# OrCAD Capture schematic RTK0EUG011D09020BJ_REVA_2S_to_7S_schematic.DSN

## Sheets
1 3_BiasSupplies: size C; title: Type-C PD Battery Charger (PB3 Shrink): Bias Supplies; rev: A; note: RTK0EUG011D09020BJ (2S to 7S)
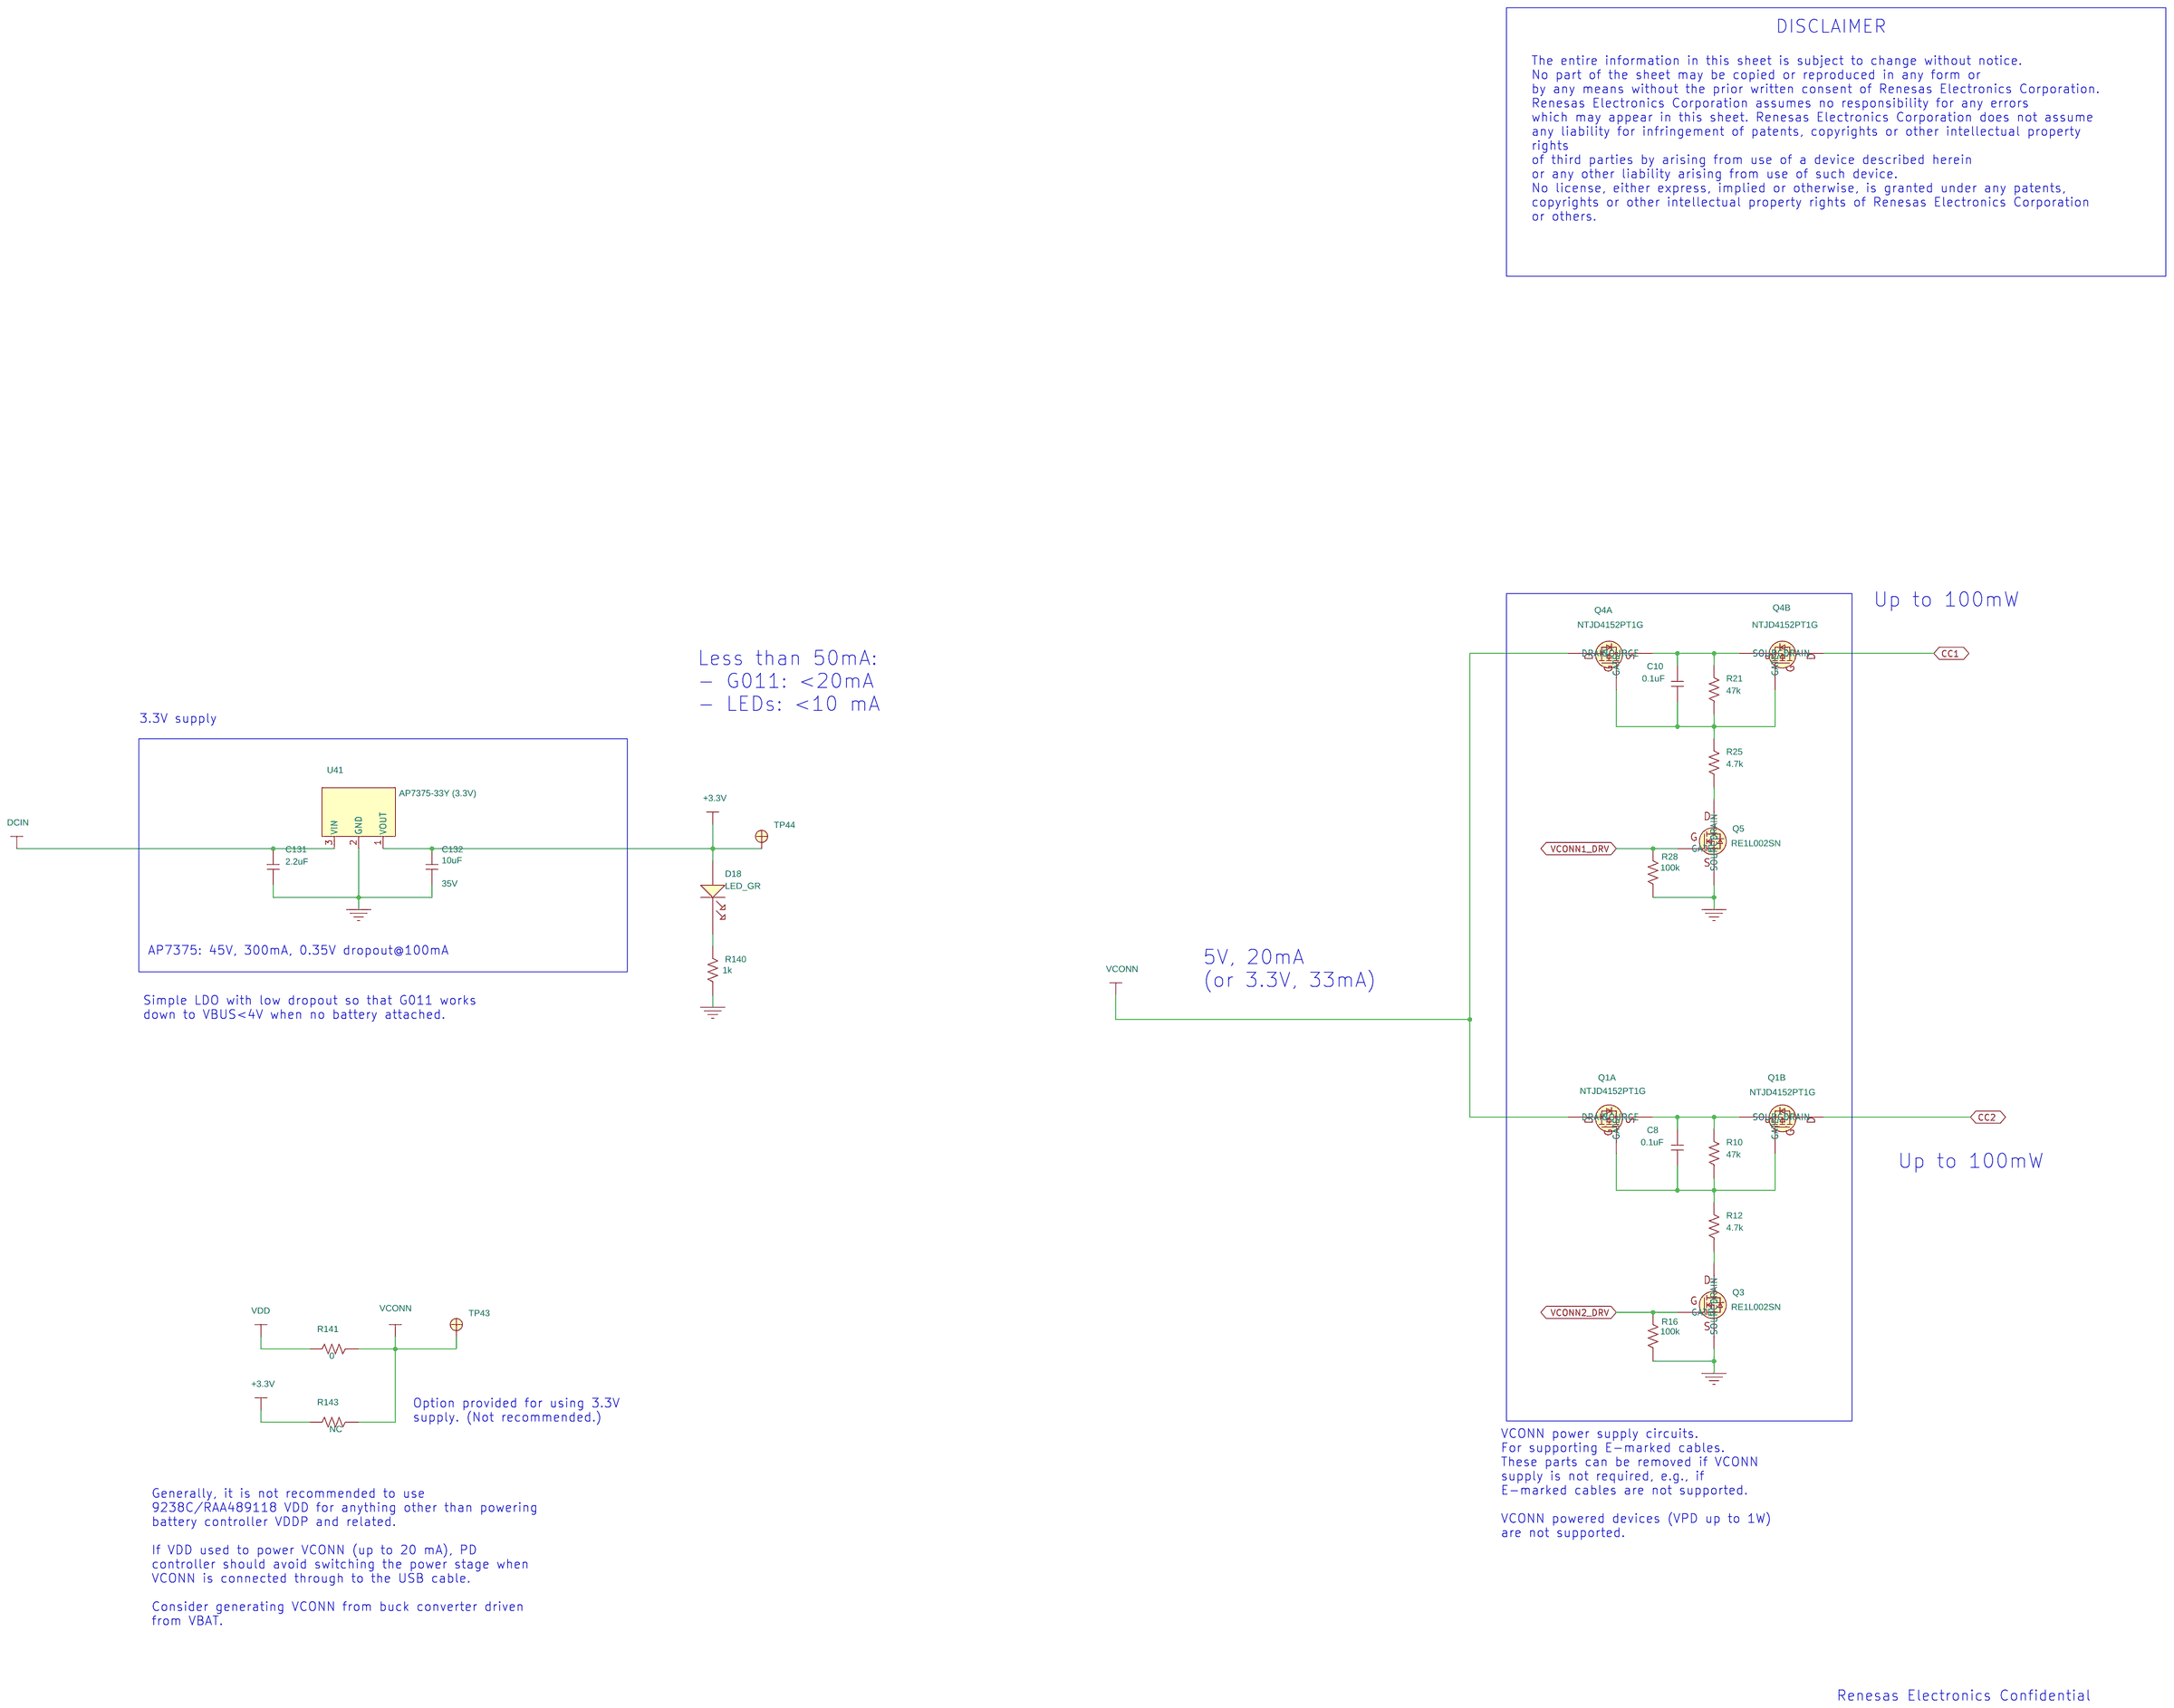
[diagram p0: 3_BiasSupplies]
2 1_Type-C R9A02G011: size C; title: Type-C PD Battery Charger: R9A02G011; note: Draft: RTK0EUG011D09020BJ
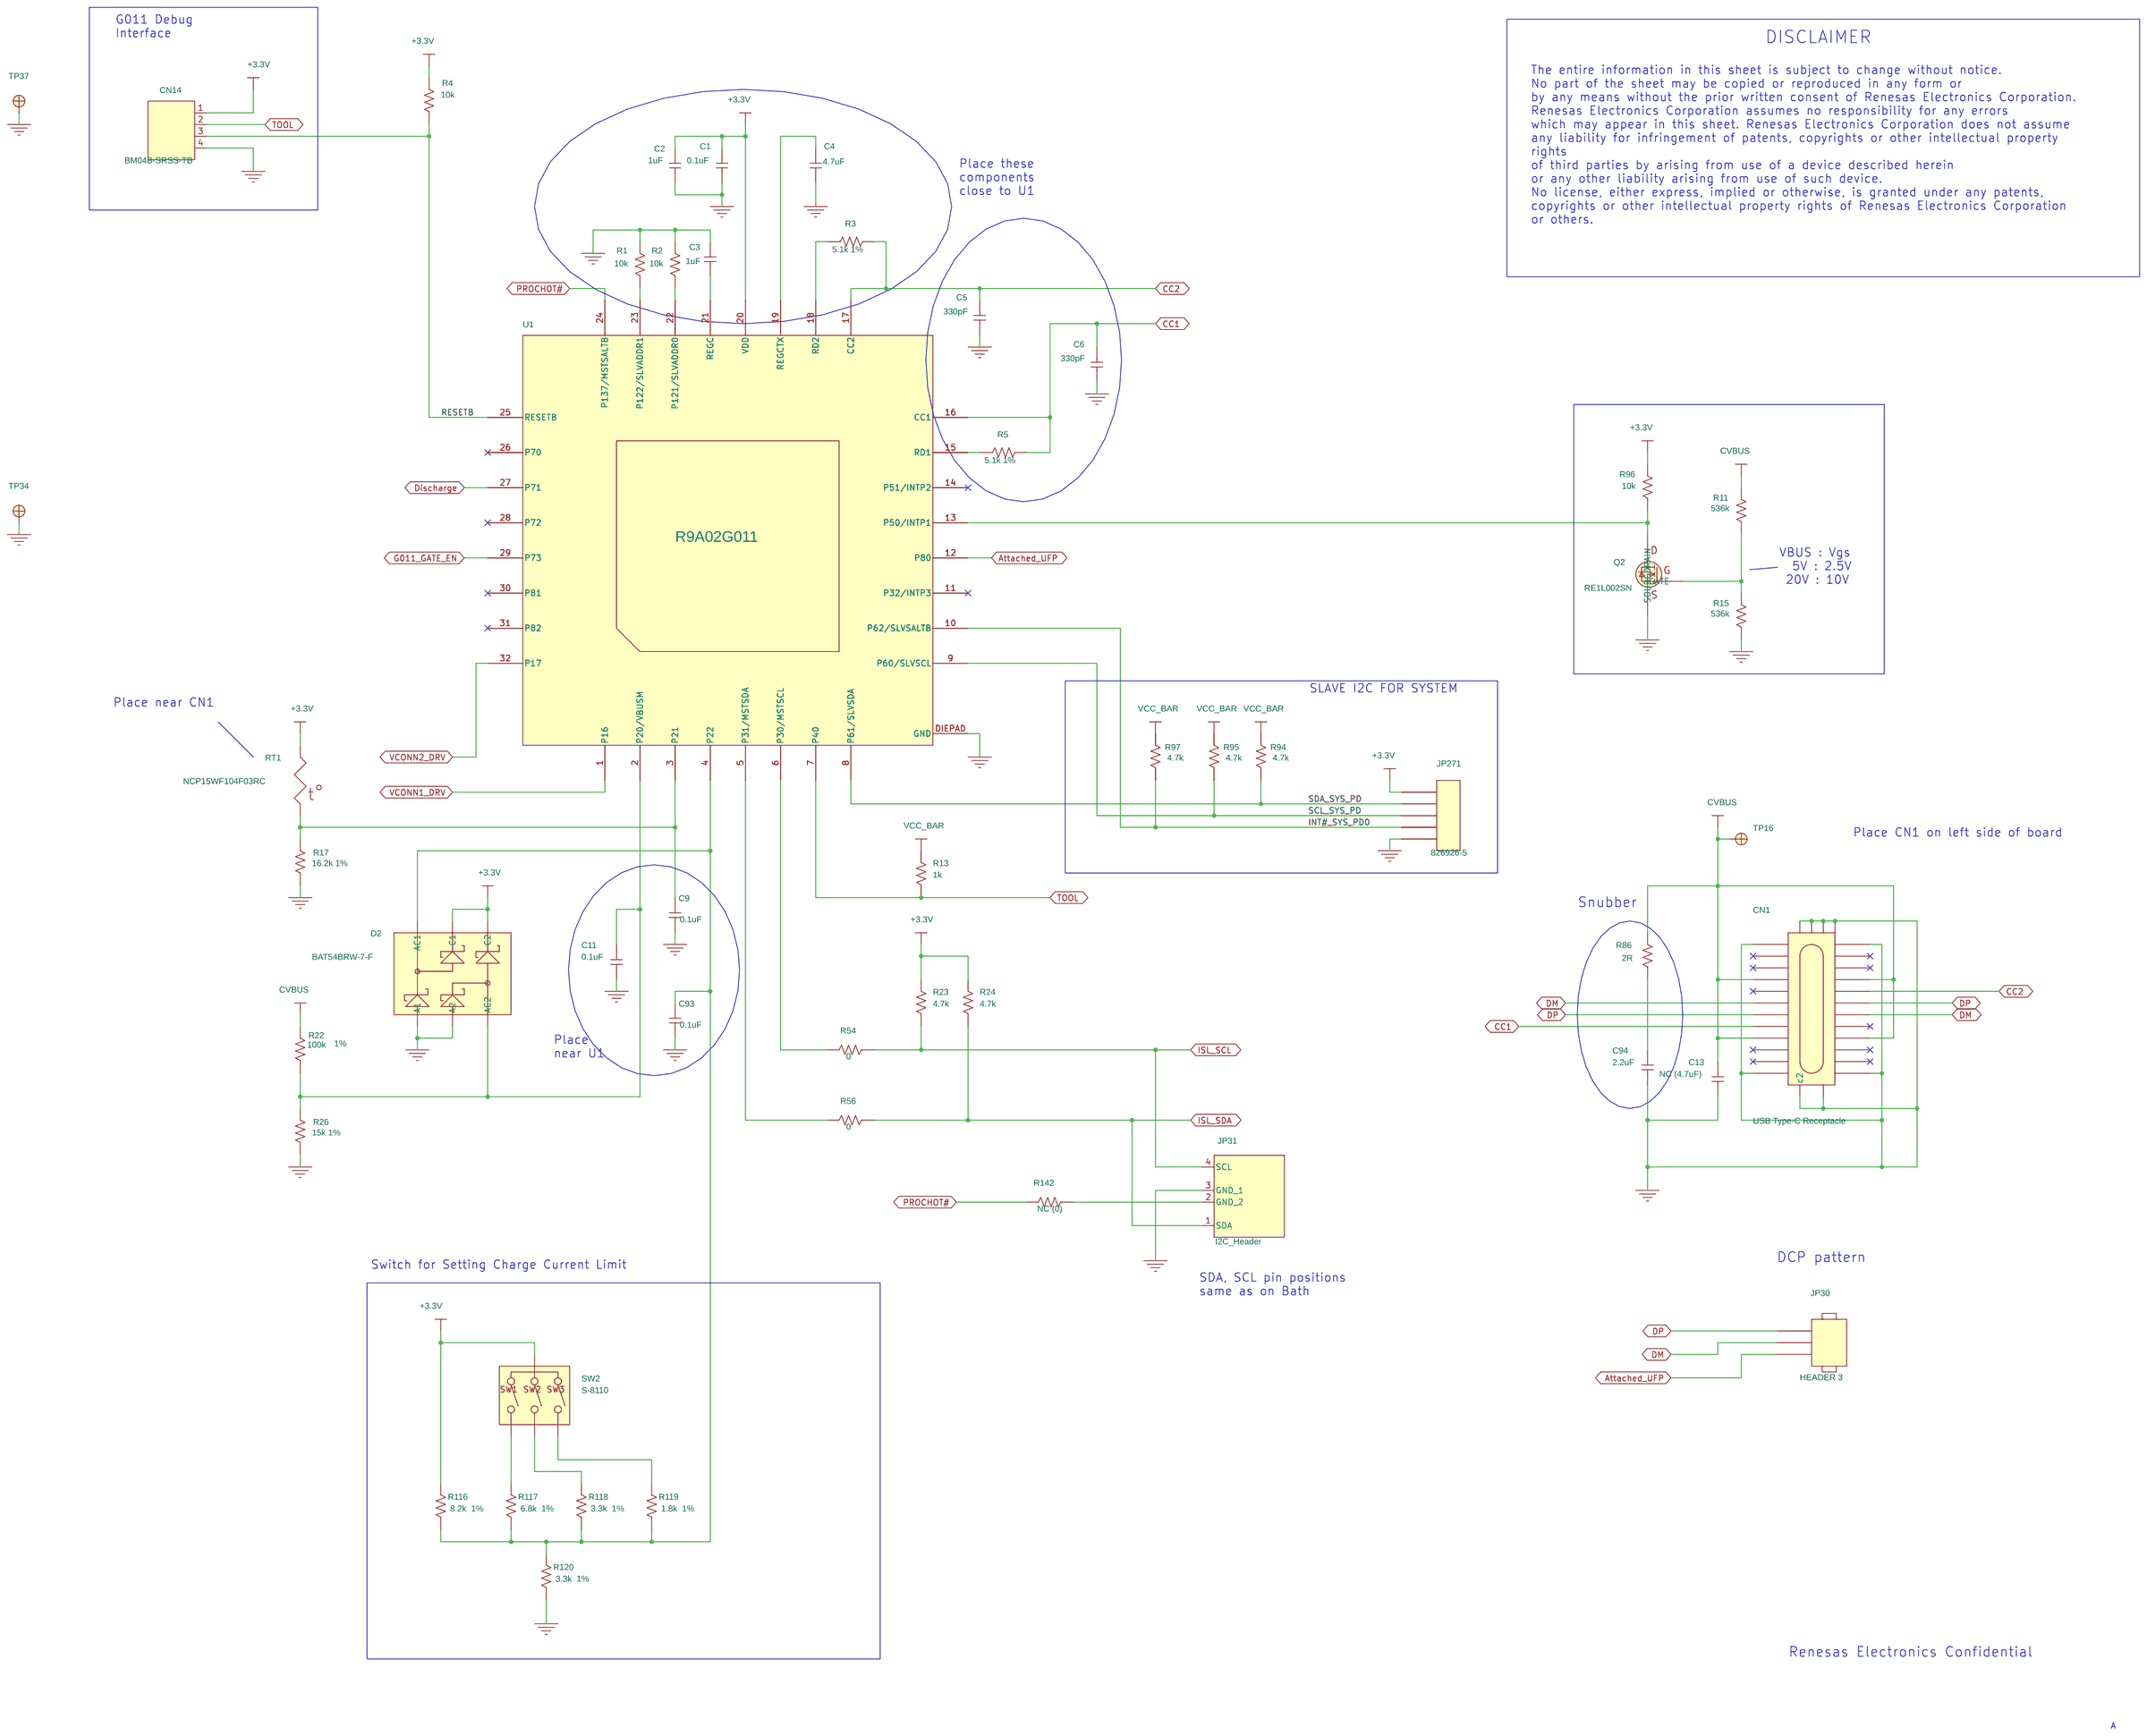
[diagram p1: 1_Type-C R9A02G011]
3 2_Type-C RAA489118: size C; title: Type-C PD Battery Charger: RAA489118
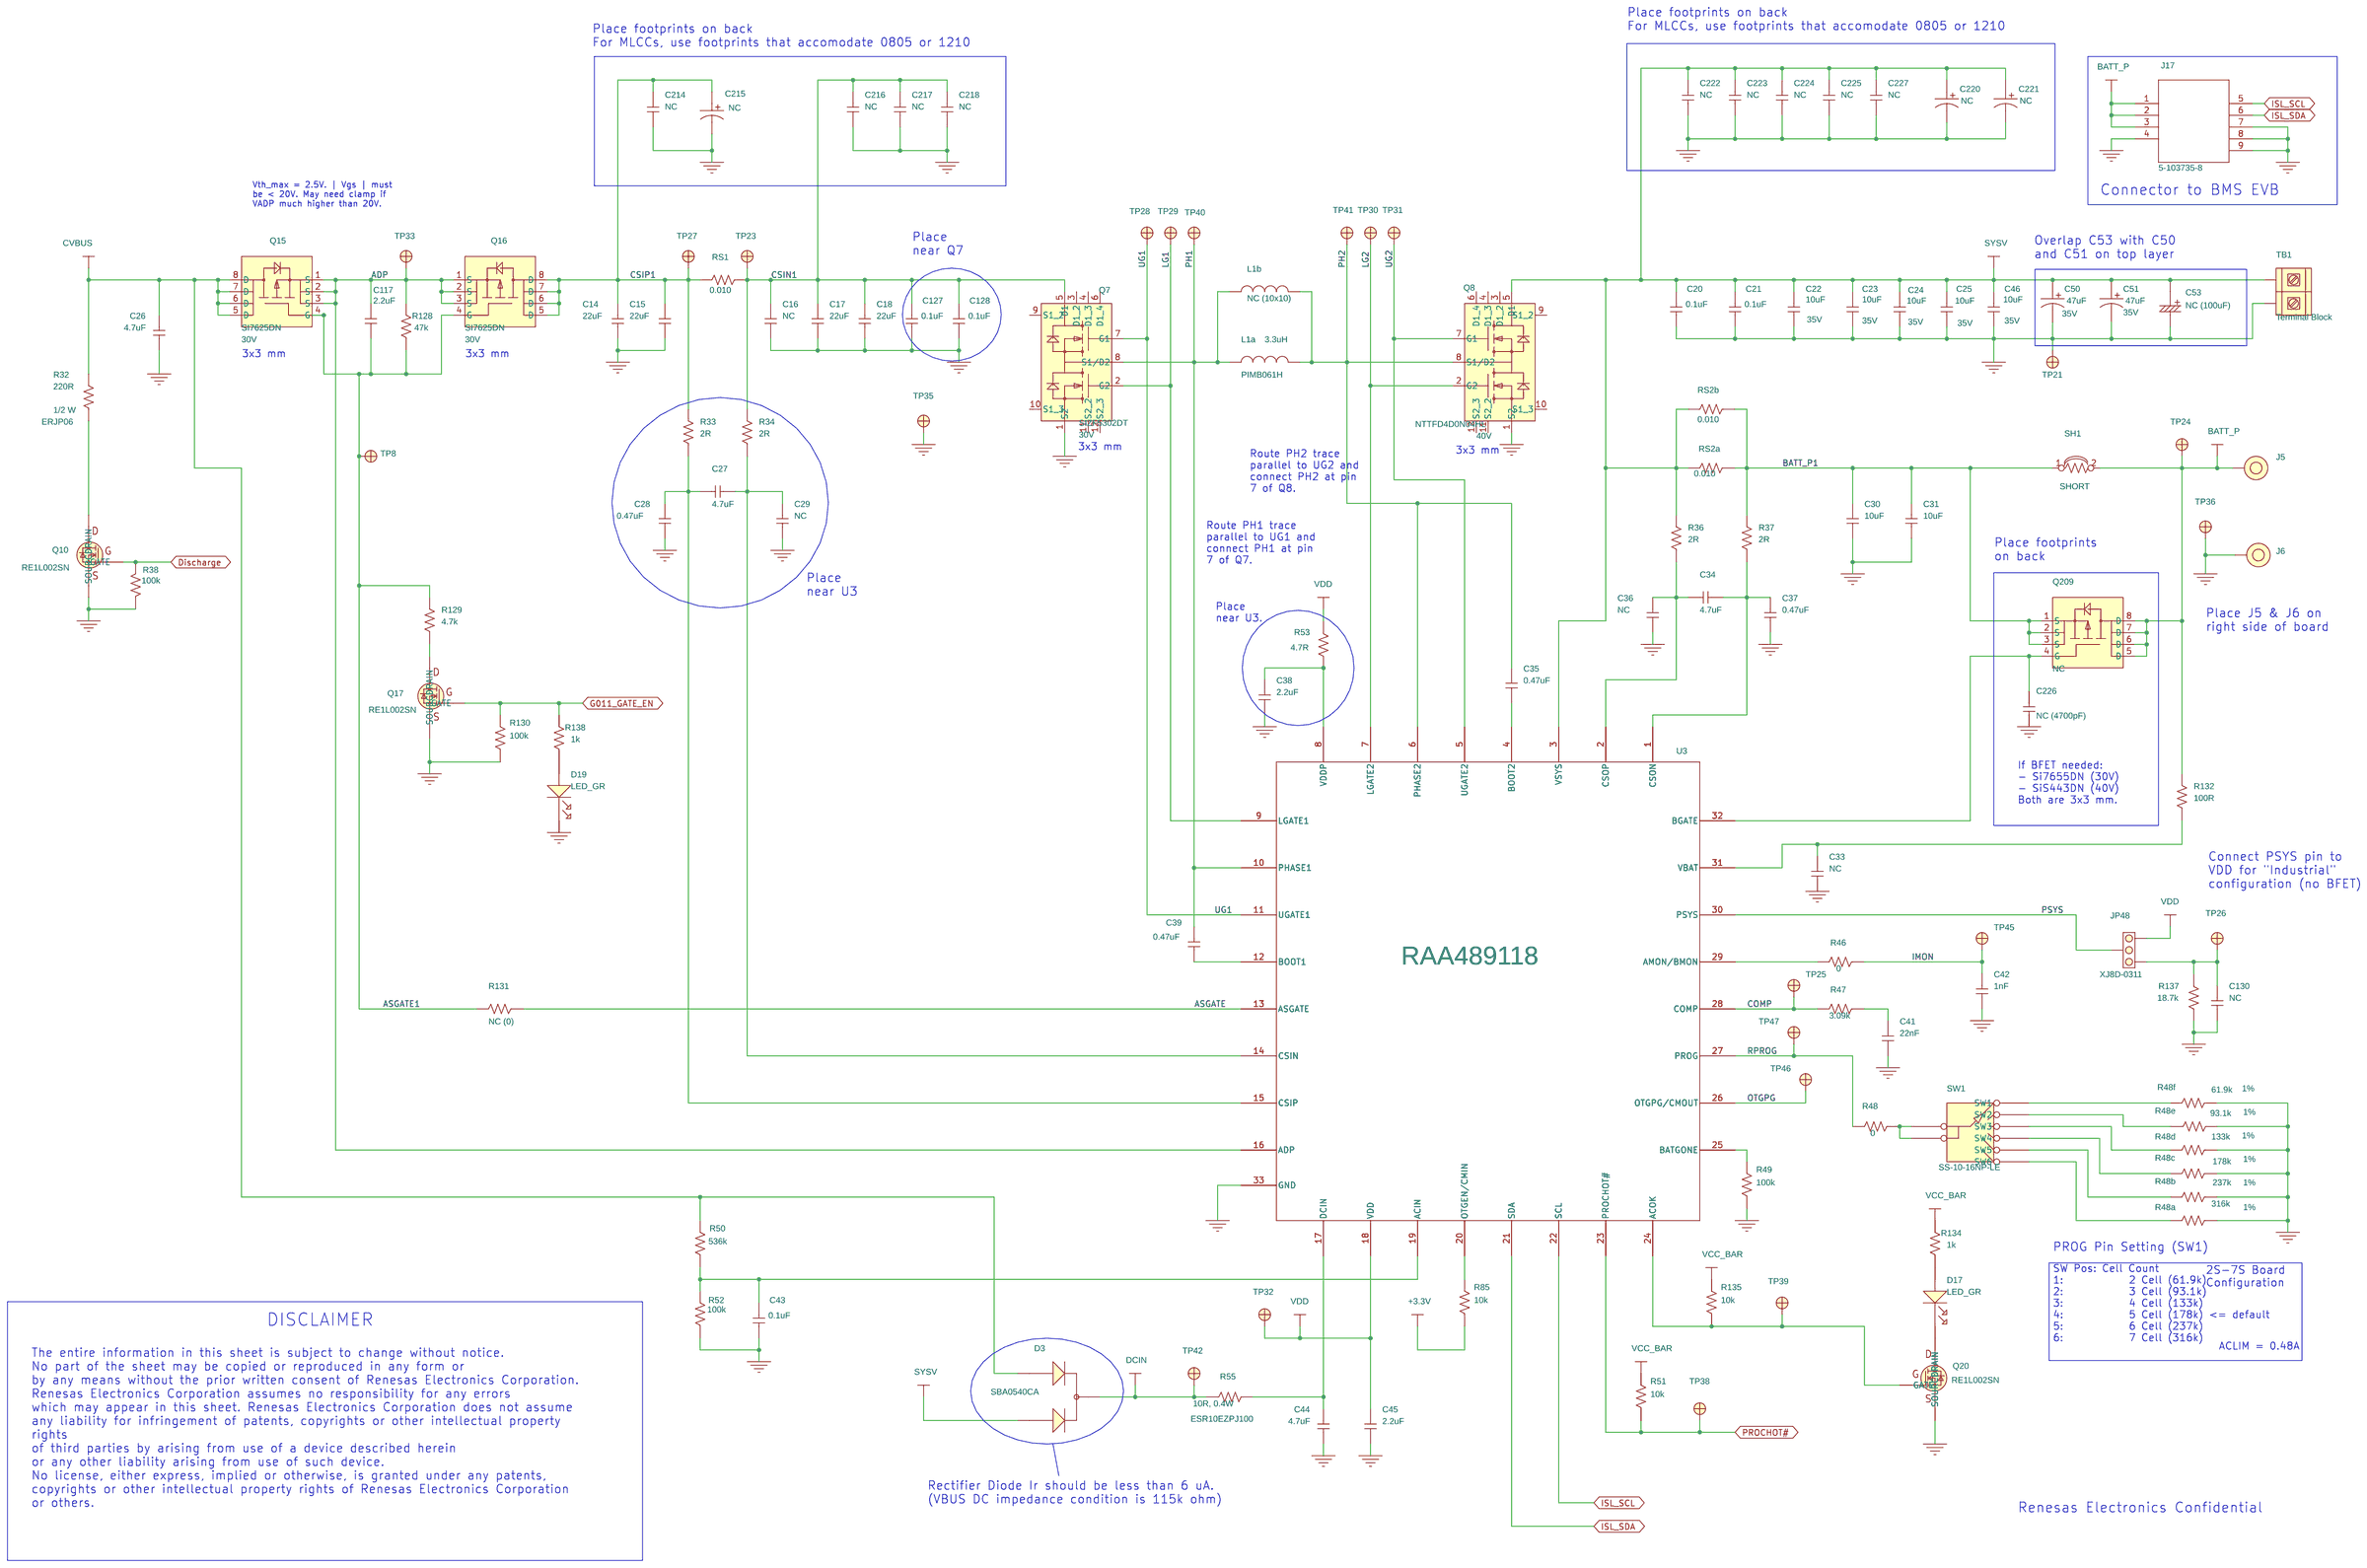
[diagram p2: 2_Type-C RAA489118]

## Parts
sheet 1_Type-C R9A02G011
C1  0.1uF  [SM0402_DELTA]
C2  1uF  [SM0603_DELTA]
C3  1uF  [SM0603_DELTA]
C4  4.7uF  [SM0603_DELTA]
C5  330pF  [SM0402_DELTA]
C6  330pF  [SM0402_DELTA]
C9  0.1uF  [SM0402_DELTA]
C11  0.1uF  [SM0402_DELTA]
C13  NC (4.7uF)  [SM0603_DELTA]
C93  0.1uF  [SM0402_DELTA]
C94  2.2uF  [SM0603_DELTA]
CN1  USB Type-C Receptacle  [DX07S024JJ2]
CN14  BM04B-SRSS-TB  [BM04B-SRSS]
D2  BAT54BRW-7-F  [SOT363-6]
JP30  HEADER 3  [CONN-1X3]
JP31  I2C_Header  [CON_MOLEX_22-28-8041]
JP271  826926-5  [CONN-1x5]
Q2  RE1L002SN  [SC-89]
R1  10k  [SM0402_DELTA]
R2  10k  [SM0402_DELTA]
R3  5.1k 1%  [SM0402_DELTA]
R4  10k  [SM0402_DELTA]
R5  5.1k 1%  [SM0402_DELTA]
R11  536k  [SM0402_DELTA]
R13  1k  [SM0603_DELTA]
R15  536k  [SM0402_DELTA]
R17  16.2k 1%  [SM0603_DELTA]
R22  100k  [SM0402_DELTA]
R23  4.7k  [SM0603_DELTA]
R24  4.7k  [SM0603_DELTA]
R26  15k 1%  [SM0603_DELTA]
R54  0  [SM0603_DELTA]
R56  0  [SM0603_DELTA]
R86  2R  [SM0603_DELTA]
R94  4.7k  [SM0603_DELTA]
R95  4.7k  [SM0603_DELTA]
R96  10k  [SM0402_DELTA]
R97  4.7k  [SM0603_DELTA]
R116  8.2k  1%  [SM0603_DELTA]
R117  6.8k  1%  [SM0603_DELTA]
R118  3.3k  1%  [SM0603_DELTA]
R119  1.8k  1%  [SM0603_DELTA]
R120  3.3k  1%  [SM0603_DELTA]
R142  NC (0)  [SM0603_DELTA]
RT1  NCP15WF104F03RC  [SM0402_DELTA]
SW2  S-8110  [S-8110]
TP16  KEYSTONE-PN-500X-100P40H  [MTP500X]
TP34  KEYSTONE-PN-1502-150p100h  [TP-150C100P-RTP]
TP37  KEYSTONE-PN-1502-150p100h  [TP-150C100P-RTP]
U1  R9A02G011  [QFN32P_5X5_2]
sheet 2_Type-C RAA489118
C14  22uF  [SM0805_DELTA]
C15  22uF  [SM0805_DELTA]
C16  NC  [SM0805_DELTA]
C17  22uF  [SM0805_DELTA]
C18  22uF  [SM0805_DELTA]
C20  0.1uF  [SM0402_DELTA]
C21  0.1uF  [SM0402_DELTA]
C22  10uF  [SM0805_DELTA]
C23  10uF  [SM0805_DELTA]
C24  10uF  [SM0805_DELTA]
C25  10uF  [SM0805_DELTA]
C26  4.7uF  [SM0603_DELTA]
C27  4.7uF  [SM0603_DELTA]
C28  0.47uF  [SM0603_DELTA]
C29  NC  [SM0603_DELTA]
C30  10uF  [SM0805_DELTA]
C31  10uF  [SM0805_DELTA]
C33  NC  [SM0603_DELTA]
C34  4.7uF  [SM0603_DELTA]
C35  0.47uF  [SM0603_DELTA]
C36  NC  [SM0603_DELTA]
C37  0.47uF  [SM0603_DELTA]
C38  2.2uF  [SM0603_DELTA]
C39  0.47uF  [SM0603_DELTA]
C41  22nF  [SM0603_DELTA]
C42  1nF  [SM0603_DELTA]
C43  0.1uF  [SM0402_DELTA]
C44  4.7uF  [SM0603_DELTA]
C45  2.2uF  [SM0603_DELTA]
C46  10uF  [SM0805_DELTA]
C50  47uF  [CAP_SANYO_D2]
C51  47uF  [CAP_SANYO_D2]
C53  NC (100uF)  [ALM_SMT_D8]
C117  2.2uF  [SM0805_DELTA]
C127  0.1uF  [SM0402_DELTA]
C128  0.1uF  [SM0402_DELTA]
C130  NC  [SM0603_DELTA]
C214  NC  [SM1210_DELTA]
C215  NC  [SM3528]
C216  NC  [SM1210_DELTA]
C217  NC  [SM1210_DELTA]
C218  NC  [SM1210_DELTA]
C220  NC  [CAP_SANYO_D2]
C221  NC  [CAP_SANYO_D2]
C222  NC  [SM1210_DELTA]
C223  NC  [SM1210_DELTA]
C224  NC  [SM1210_DELTA]
C225  NC  [SM1210_DELTA]
C226  NC (4700pF)  [SM0603_DELTA]
C227  NC  [SM1210_DELTA]
D3  SBA0540CA  [SOT23]
D17  LED_GR  [LED1608]
D19  LED_GR  [LED1608]
J5  Banana_Jack_Red  [111-07XX-001]
J6  Banana_Jack_Black  [111-07XX-001]
J17  5-103735-8  [TE_5-103735-8]
JP48  XJ8D-0311  [JUMPER3]
L1a  3.3uH  [IND_PIMB061H]
L1b  NC (10x10)  [ETQP4LXXXWFC]
Q7  SIZF5302DT  [POWERCLIP_33SYMM]
Q8  NTTFD4D0N04HL  [POWERCLIP_33SYMM]
Q10  RE1L002SN  [SC-89]
Q15  SI7625DN  [PWRPAK_SINGLE_1212-8]
Q16  SI7625DN  [PWRPAK_SINGLE_1212-8]
Q17  RE1L002SN  [SC-89]
Q20  RE1L002SN  [SC-89]
Q209  NC  [PWRPAK_SINGLE_1212-8]
R32  220R  [SM0805_DELTA]
R33  2R  [SM0603_DELTA]
R34  2R  [SM0603_DELTA]
R36  2R  [SM0603_DELTA]
R37  2R  [SM0603_DELTA]
R38  100k  [SM0402_DELTA]
R46  0  [SM0603_DELTA]
R47  3.09k  [SM0603_DELTA]
R48  0  [SM0603_DELTA]
R48a  316k  [SM0603_DELTA]
R48b  237k  [SM0603_DELTA]
R48c  178k  [SM0603_DELTA]
R48d  133k  [SM0603_DELTA]
R48e  93.1k  [SM0603_DELTA]
R48f  61.9k  [SM0603_DELTA]
R49  100k  [SM0402_DELTA]
R50  536k  [SM0402_DELTA]
R51  10k  [SM0402_DELTA]
R52  100k  [SM0402_DELTA]
R53  4.7R  [SM0603_DELTA]
R55  10R, 0.4W  [SM0805_DELTA]
R85  10k  [SM0402_DELTA]
R128  47k  [SM0603_DELTA]
R129  4.7k  [SM0603_DELTA]
R130  100k  [SM0402_DELTA]
R131  NC (0)  [SM0603_DELTA]
R132  100R  [SM0603_delta]
R134  1k  [SM0603_DELTA]
R135  10k  [SM0402_DELTA]
R137  18.7k  [SM0603_DELTA]
R138  1k  [SM0603_DELTA]
RS1  0.010  [SM1206_DELTA]
RS2a  0.010  [SM1206_DELTA]
RS2b  0.010  [SM1206_DELTA]
SH1  SHORT  [SM1206]
SW1  SS-10-16NP-LE  [SWITCH_TH-8N]
TB1  Terminal Block  [1729018]
TP8  KEYSTONE-PN-500X-100P40H  [MTP500X]
TP21  KEYSTONE-PN-1502-150p100h  [TP-150C100P-RTP]
TP23  KEYSTONE-PN-500X-100P40H  [MTP500X]
TP24  KEYSTONE-PN-500X-100P40H  [MTP500X]
TP25  KEYSTONE-PN-500X-100P40H  [MTP500X]
TP26  KEYSTONE-PN-500X-100P40H  [MTP500X]
TP27  KEYSTONE-PN-500X-100P40H  [MTP500X]
TP28  KEYSTONE-PN-500X-100P40H  [MTP500X]
TP29  KEYSTONE-PN-500X-100P40H  [MTP500X]
TP30  KEYSTONE-PN-500X-100P40H  [MTP500X]
TP31  KEYSTONE-PN-500X-100P40H  [MTP500X]
TP32  KEYSTONE-PN-500X-100P40H  [MTP500X]
TP33  KEYSTONE-PN-500X-100P40H  [MTP500X]
TP35  KEYSTONE-PN-1502-150p100h  [TP-150C100P-RTP]
TP36  KEYSTONE-PN-1502-150p100h  [TP-150C100P-RTP]
TP38  KEYSTONE-PN-500X-100P40H  [MTP500X]
TP39  KEYSTONE-PN-500X-100P40H  [MTP500X]
TP40  KEYSTONE-PN-500X-100P40H  [MTP500X]
TP41  KEYSTONE-PN-500X-100P40H  [MTP500X]
TP42  KEYSTONE-PN-500X-100P40H  [MTP500X]
TP45  KEYSTONE-PN-500X-100P40H  [MTP500X]
TP46  KEYSTONE-PN-500X-100P40H  [MTP500X]
TP47  KEYSTONE-PN-500X-100P40H  [MTP500X]
U3  RAA489118  [QFN32_157X157_157_EP]
sheet 3_BiasSupplies
C8  0.1uF  [SM0402_DELTA]
C10  0.1uF  [SM0402_DELTA]
C131  2.2uF  [SM0603_DELTA]
C132  10uF  [SM0805_DELTA]
D18  LED_GR  [LED1608]
Q1  NTJD4152PT1G  [SC-70-6]  (sections A,B)
Q3  RE1L002SN  [SC-89]
Q4  NTJD4152PT1G  [SC-70-6]  (sections A,B)
Q5  RE1L002SN  [SC-89]
R10  47k  [SM0603_DELTA]
R12  4.7k  [SM0603_DELTA]
R16  100k  [SM0402_DELTA]
R21  47k  [SM0603_DELTA]
R25  4.7k  [SM0603_DELTA]
R28  100k  [SM0402_DELTA]
R140  1k  [SM0603_DELTA]
R141  0  [SM0603_DELTA]
R143  NC  [SM0603_DELTA]
TP43  KEYSTONE-PN-500X-100P40H  [MTP500X]
TP44  KEYSTONE-PN-500X-100P40H  [MTP500X]
U41  AP7375-33Y (3.3V)  [SOT89-3L]

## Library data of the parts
C1 C5 C6 C8-C11 C43 C93 = 0402_v2: VOLT: 16V
C2-C4 C13 C26 C29 C33 C36-C38 C41 C42 C44 C45 C94 C130 C131 C226 = 0603: TOLERANCE: 10%; VOLT: 25V
CN1 = USB_Type-C_Receptacle_1
CN14 = BM04B-SRSS-TB
D2 = CDBV6-54BR-G
JP30 = HEADER_3
JP31 = I2C_Header_1: CONN RCPT 4POS 0.1 TIN EDGE MNT; Digi-Key PN: WM14508-ND; Manufacturer: Molex; Part_Number: 0022053041; digikey_id: {"distributorPn":"WM14508-ND","mfr":"Molex","mpn":"0038001334"}
JP271 = CON5
Q2 Q3 Q5 Q10 Q17 Q20 = MOSFET_P_SOP8_1
R1-R5 R16 R28 R38 R49 R51 R52 R85 R96 R130 R135 = 0402
R11 R15 R50 = 0402: Tolearance: 1%
R10 R12 R13 R17 R21 R23-R26 R33 R34 R36 R37 R46-R48 R53 R54 R56 R86 R94 R95 R97 R116-R120 R128 R129 R131 R132 R134 R137 R138 R140-R143 = 0603_v2
R22 = 0402: Tolerance: 1%
RT1 = NTC
SW2 = S-8110
TP8 TP16 TP23-TP33 TP38-TP47 = KEYSTONE-PN-500X-100P40H
TP21 TP34-TP37 = KEYSTONE-PN-1502-150p100h: TERM TURRET SINGLE L=7.65MM TIN; Digi-Key PN: 36-1598-2-ND; Manufacturer: Keystone Electronics; Part_Number: 1598-2; digikey_id: {"distributorPn":"36-1598-2-ND","mfr":"Keystone Electronics","mpn":"1598-2"}
U1 = uPD720230_1
C14 C30 C31 C117 = 0805_v2
C15-C18 C22-C25 C46 C132 = 0805_v2: VOLT: 35V
C20 C21 C127 C128 = 0402_v2: VOLT: 35V
C27 C34 = 0603
C28 = 0603: TOLERANCE: 10%; VOLT: 35V
C35 C39 = 0603: DIEL: X5R; VOLT: 50V
C50 C51 C220 C221 = SANYO-POSCAP-D2: TOLERANCE: 20%; volt: 35V
C53 = CAP_NP_0
C214 C216-C218 C222-C225 C227 = 1210
C215 = TANT-CASE-D
D3 = BAT54C_SOT: Voltage: 40V
D17-D19 = LED_1
J5 J6 = Banana_J
J17 = 5-103735-8
JP48 = XJ8D-0311
L1a = COILCRAFT-CHIP-IND-0805: PART NUMBER: PIMB061H; TOLERANCE: 20%
L1b = PANASONIC-ETQP4L
Q7 = DualFET_LP_FS: Rating: 30V
Q8 = DualFET_LP_FS: Rating: 40V
Q15 Q16 Q209 = Si7655DN_4: TRANSISTOR,P-CHANNEL,SMD,SOT23,-60V,-180mA,ROHS; CLASS: DISCRETE; PART_NUMBER: Si7655DN; Rating: 30V
R32 = 0805: Part Number: ERJP06; Power Rating: 1/2 W
R48a R48b R48c R48d R48f = 0603_v2: TOLERANCE: 1%
R48e = 0201: TOLERANCE: 1%
R55 = 0805: Part Number: ESR10EZPJ100
RS1 RS2a RS2b = 0805: TOLERANCE: 1%
SH1 = RES_Short_1: RES 0 OHM JUMPER 1206; Digi-Key PN: 2019-TLRZ2BTTDDKR-ND; Manufacturer: KOA Speer Electronics, Inc.; Part_Number: TLRZ2BTTD; digikey_id: {"distributorPn":"2019-TLRZ2BTTDDKR-ND","mfr":"KOA Speer Electronics, Inc.","mpn":"TLRZ2BTTD","ul":{"uid":"42e93078-2120-11ec-9033-0a34d6323d74","url":"https://app.ultralibrarian.com/details/42e93078-2120-11ec-9033-0a34d6323d74/KOA-Speer/TLRZ2BTTD","mpn_store":null,"last_check":"2023-05-15T19:07:03.985Z","has_reference_designs":false}}
SW1 = SW-ROTARY_1P-6W_2
TB1 = 1729018
U3 = ISL95538B_2
Q1 Q4 = MOSFET_P+P_1
U41 = AP7215_1: Diodes Inc: 600mA CMOS LDO Regulator; Input Voltage: 24V; Manufacturer: Diodes Incorporated; Part Number: AP7215-33YG-13; Part Type: Regulator; Rating: 150 mA; Temp(T/C): -40°C ~ 125°C

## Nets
+3.3V: C1.2 C2.2 C132.2 CN14.1 D2.4(C2) D2.5(C1) D18.ANODE JP271.1 R4.2 R13.2 R23.2 R24.2 R51.2 R85.1 R94.2 R95.2 R96.2 R97.2 R116.2 R134.2 R135.2 R143.2 RT1.1 SW2.C TP44.1 U1.20(VDD) U41.1(VOUT)
GND: C1.1 C2.1 C3.2 C4.1 C5.1 C6.1 C9.1 C11.1 C13.1 C14.1 C15.1 C16.1 C17.1 C18.1 C20.1 C21.1 C22.1 C23.1 C24.1 C25.1 C26.1 C28.1 C29.1 C30.1 C31.1 C33.1 C36.1 C37.1 C38.1 C41.1 C42.1 C43.1 C44.1 C45.1 C46.1 C50.2(N) C51.2(N) C53.2 C93.1 C94.1 C127.1 C128.1 C130.1 C131.1 C132.1 C214.1 C215.2(N) C216.1 C217.1 C218.1 C220.2(N) C221.2(N) C222.1 C223.1 C224.1 C225.1 C226.1 C227.1 CN1.A1 CN1.A12 CN1.B1 CN1.B12 CN1.C1 CN1.C2(c2) CN1.C3 CN1.C4 CN1.C5 CN1.C6 CN14.4 D2.1(A1) D2.2(A2) D19.CATHODE J6.1 J17.4 J17.7 J17.8 J17.9 JP31.3(GND_1) JP271.5 Q2.2(SOURCE) Q3.2(SOURCE) Q5.2(SOURCE) Q7.1(S2) Q8.1(S2) Q10.2(SOURCE) Q17.2(SOURCE) Q20.2(SOURCE) R1.2 R2.2 R15.1 R16.1 R17.1 R26.1 R28.1 R38.1 R48a.1 R48b.1 R48c.1 R48d.1 R48e.2 R48f.1 R49.1 R52.1 R120.1 R130.1 R137.2 R140.1 TB1.1 TP21.1 TP34.1 TP35.1 TP36.1 TP37.1 U1.DIEPAD(GND) U3.33(GND) U41.2(GND)
VDD: C45.2 JP48.1 R53.1 R141.2 TP32.1 U3.18(VDD)
ADP: C117.2 Q15.1(S) Q15.2(S) Q15.3(S) Q16.1(S) Q16.2(S) Q16.3(S) R128.2 TP33.1 U3.16(ADP)
ASGATE: R131.1 U3.13(ASGATE)
ASGATE1: C117.1 Q15.4(G) Q16.4(G) R128.1 R129.2 R131.2 TP8.1
Attached_UFP: JP30.3 U1.12(P80)
Batt_P: J5.1 J17.1 J17.2 J17.3 Q209.5(D) Q209.6(D) Q209.7(D) Q209.8(D) R132.2 SH1.2 TP24.1
BATT_P1: C30.2 C31.2 Q209.1(S) Q209.2(S) Q209.3(S) R37.2 RS2a.1 RS2b.1 SH1.1
CC1: C6.2 CN1.A5 Q4.3(DRAIN) R5.2 U1.16(CC1)
CC2: C5.2 CN1.B5 Q1.3(DRAIN) R3.2 U1.17(CC2)
COMP: R47.2 TP25.1 U3.28(COMP)
CSIN1: C16.2 C17.2 C18.2 C127.2 C128.2 C216.2 C217.2 C218.2 Q7.5(D1) R34.2 RS1.1 TP23.1
CSIP1: C14.2 C15.2 C214.2 C215.1(P) Q16.5(D) Q16.6(D) Q16.7(D) Q16.8(D) R33.2 RS1.2 TP27.1
cVBUS: C13.2 C26.2 CN1.A4 CN1.A9 CN1.B4 CN1.B9 D3.1(C1) Q15.5(D) Q15.6(D) Q15.7(D) Q15.8(D) R11.2 R22.2 R32.2 R50.2 R86.2 TP16.1
DCin: C131.2 D3.3(A) R55.1 TP42.1 U41.3(VIN)
Discharge: Q10.1(GATE) R38.2 U1.27(P71)
DM: CN1.A7 CN1.B7 JP30.2
DP: CN1.A6 CN1.B6 JP30.1
G011_GATE_EN: Q17.1(GATE) R130.2 R138.2 U1.29(P73)
IMON: C42.2 R46.1 TP45.1
INT#_SYS_PD0: JP271.4 R97.1 U1.10(P62/SLVSALTB)
ISL_SCL: J17.5 JP31.4(SCL) R23.1 R54.1 U3.22(SCL)
ISL_SDA: J17.6 JP31.1(SDA) R24.1 R56.1 U3.21(SDA)
LG1: Q7.2(G2) TP29.1 U3.9(LGATE1)
LG2: Q8.2(G2) TP30.1 U3.7(LGATE2)
OTGPG: TP46.1 U3.26(OTGPG/CMOUT)
PH1: C39.1 L1a.1 L1b.2 Q7.8(S1/D2) TP40.1 U3.10(PHASE1)
PH2: C35.1 L1a.2 L1b.1 Q8.8(S1/D2) TP41.1 U3.6(PHASE2)
PROCHOT#: R51.1 R142.2 TP38.1 U1.24(P137/MSTSALTB) U3.23(PROCHOT#)
PSYS: JP48.2 U3.30(PSYS)
RESETB: CN14.3 R4.1 U1.25(RESETB)
RPROG: R48.2 TP47.1 U3.27(PROG)
SCL_SYS_PD: JP271.3 R95.1 U1.9(P60/SLVSCL)
SDA_SYS_PD: JP271.2 R94.1 U1.8(P61/SLVSDA)
SysV: C20.2 C21.2 C22.2 C23.2 C24.2 C25.2 C46.2 C50.1(P) C51.1(P) C53.1 C220.1(P) C221.1(P) C222.2 C223.2 C224.2 C225.2 C227.2 D3.2(C2) Q8.5(D1) R36.2 RS2a.2 RS2b.2 TB1.2 U3.3(VSYS)
TOOL: CN14.2 R13.1 U1.7(P40)
UG1: Q7.7(G1) TP28.1 U3.11(UGATE1)
UG2: Q8.7(G1) TP31.1 U3.5(UGATE2)
VCONN: Q1.6(DRAIN) Q4.6(DRAIN) R141.1 R143.1 TP43.1
VCONN1_DRV: Q5.1(GATE) R28.2 U1.1(P16)
VCONN2_DRV: Q3.1(GATE) R16.2 U1.32(P17)
N15200226: R2.1 U1.22(P121/SLVADDR0)
N15200258: R56.2 U1.5(P31/MSTSDA)
N15200262: R54.2 U1.6(P30/MSTSCL)
N15200472: R1.1 U1.23(P122/SLVADDR1)
N15200728: R3.1 U1.18(RD2)
N15200736: R5.1 U1.15(RD1)
N15200912: C3.1 U1.21(REGC)
N15284290: C27.1 C28.2 R33.1 U3.15(CSIP)
N15284294: C27.2 C29.2 R34.1 U3.14(CSIN)
N15284470: C43.2 R50.1 R52.2 U3.19(ACIN)
N15284522: R46.2 U3.29(AMON/BMON)
N15284718: C41.2 R47.1
N15284978: C44.2 R55.2 U3.17(DCIN)
N15285662: C34.1 C36.2 R36.1 U3.2(CSOP)
N15285666: C34.2 C37.2 R37.1 U3.1(CSON)
N15285726: C226.2 Q209.4(G) U3.32(BGATE)
N15285742: C33.2 R132.1 U3.31(VBAT)
N15285822: C38.2 R53.2 U3.8(VDDP)
N15285862: R49.2 U3.25(BATGONE)
N15285922: Q10.3(DRAIN) R32.1
N16775177: C11.2 D2.3(AC2) R22.1 R26.2 U1.2(P20/VBUSM)
N16775283: C9.2 R17.2 RT1.2 U1.3(P21)
N16775887: C93.2 D2.6(AC1) R116.1 R117.1 R118.1 R119.1 R120.2 U1.4(P22)
N16854744: Q2.3(DRAIN) R96.1 U1.13(P50/INTP1)
N16854902: Q2.1(GATE) R11.1 R15.2
N16925191: R85.2 U3.20(OTGEN/CMIN)
N16929732: C94.2 R86.1
N17029936: C8.1 Q1.2(GATE) Q1.5(GATE) R10.1 R12.2
N17029938: C8.2 Q1.1(SOURCE) Q1.4(SOURCE) R10.2
N17029966: Q3.3(DRAIN) R12.1
N17030035: C10.1 Q4.2(GATE) Q4.5(GATE) R21.1 R25.2
N17030049: C10.2 Q4.1(SOURCE) Q4.4(SOURCE) R21.2
N17183831: C35.2 U3.4(BOOT2)
N17268982: Q20.1(GATE) R135.1 TP39.1 U3.24(ACOK)
N17286340: C4.2 U1.19(REGCTX)
N17317412: C130.2 JP48.3 R137.1 TP26.1
N17341810: C39.2 U3.12(BOOT1)
N17357543: Q17.3(DRAIN) R129.1
N17369918: Q5.3(DRAIN) R25.1
N17406141: JP31.2(GND) R142.1
N17412587: D18.CATHODE R140.2
N17417629: R117.2 SW2.1
N17417631: R118.2 SW2.2
N17417633: R119.2 SW2.4
N17435711: R48f.2 SW1.1(SW1)
N17435721: R48e.1 SW1.2(SW2)
N17435729: R48.1 SW1.7 SW1.8
N17435733: R48d.2 SW1.3(SW3)
N17435747: R48c.2 SW1.4(SW4)
N17435757: R48b.2 SW1.5(SW5)
N17435769: R48a.2 SW1.6(SW6)
N17541088: D19.ANODE R138.1
N17541089: D17.ANODE R134.1
N17541092: D17.CATHODE Q20.3(DRAIN)

Not connected (* = marked no-connect by the designer): CN1 A2* A3* A8* A10* A11* B2* B3* B8* B10* B11*; Q7 3(D1_2) 4(D1_3) 6(D1_4) 9(S1_2) 10(S1_3) 11(S2_2) 12(S2_3); Q8 3(D1_2) 4(D1_3) 6(D1_4) 9(S1_2) 10(S1_3) 11(S2_2) 12(S2_3); U1 11(P32/INTP3)* 14(P51/INTP2)* 26(P70)* 28(P72)* 30(P81)* 31(P82)*

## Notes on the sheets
sheet 1
- DISCLAIMER
- The entire information in this sheet is subject to change without notice.
  No part of the sheet may be copied or reproduced in any form or
  by any means without the prior written consent of Renesas Electronics Corporation.
  Renesas Electronics Corporation assumes no responsibility for any errors
  which may appear in this sheet. Renesas Electronics Corporation does not assume
  any liability for infringement of patents, copyrights or other intellectual property
  rights
  of third parties by arising from use of a device described herein
  or any other liability arising from use of such device.
  No license, either express, implied or otherwise, is granted under any patents,
  copyrights or other intellectual property rights of Renesas Electronics Corporation
  or others.
- Up to 100mW
- Less than 50mA:
  - G011: <20mA
  - LEDs: <10 mA
- 3.3V supply
- AP7375: 45V, 300mA, 0.35V dropout@100mA
- 5V, 20mA
  (or 3.3V, 33mA)
- Simple LDO with low dropout so that G011 works
  down to VBUS<4V when no battery attached.
- Up to 100mW
- Option provided for using 3.3V
  supply. (Not recommended.)
- VCONN power supply circuits.
  For supporting E-marked cables.
  These parts can be removed if VCONN
  supply is not required, e.g., if
  E-marked cables are not supported.
  VCONN powered devices (VPD up to 1W)
  are not supported.
- Generally, it is not recommended to use
  9238C/RAA489118 VDD for anything other than powering
  battery controller VDDP and related.
  If VDD used to power VCONN (up to 20 mA), PD
  controller should avoid switching the power stage when
  VCONN is connected through to the USB cable.
  Consider generating VCONN from buck converter driven
  from VBAT.
- Renesas Electronics Confidential
sheet 2
- G011 Debug
  Interface
- DISCLAIMER
- The entire information in this sheet is subject to change without notice.
  No part of the sheet may be copied or reproduced in any form or
  by any means without the prior written consent of Renesas Electronics Corporation.
  Renesas Electronics Corporation assumes no responsibility for any errors
  which may appear in this sheet. Renesas Electronics Corporation does not assume
  any liability for infringement of patents, copyrights or other intellectual property
  rights
  of third parties by arising from use of a device described herein
  or any other liability arising from use of such device.
  No license, either express, implied or otherwise, is granted under any patents,
  copyrights or other intellectual property rights of Renesas Electronics Corporation
  or others.
- Place these
  components
  close to U1
- VBUS : Vgs
    5V : 2.5V
   20V : 10V
- SLAVE I2C FOR SYSTEM
- Place near CN1
- Place CN1 on left side of board
- Snubber
- Place
  near U1
- DCP pattern
- Switch for Setting Charge Current Limit
- SDA, SCL pin positions
  same as on Bath
- Renesas Electronics Confidential
- A
sheet 3
- Place footprints on back
  For MLCCs, use footprints that accomodate 0805 or 1210
- Place footprints on back
  For MLCCs, use footprints that accomodate 0805 or 1210
- Vth_max = 2.5V. | Vgs | must
  be < 20V. May need clamp if
  VADP much higher than 20V.
- Connector to BMS EVB
- Place
  near Q7
- Overlap C53 with C50
  and C51 on top layer
- 3x3 mm
- 3x3 mm
- 3x3 mm
- 3x3 mm
- Route PH2 trace
  parallel to UG2 and
  connect PH2 at pin
  7 of Q8.
- Route PH1 trace
  parallel to UG1 and
  connect PH1 at pin
  7 of Q7.
- Place footprints
  on back
- Place
  near U3
- Place
  near U3.
- Place J5 & J6 on
  right side of board
- If BFET needed:
  - Si7655DN (30V)
  - SiS443DN (40V)
  Both are 3x3 mm.
- Connect PSYS pin to
  VDD for "Industrial"
  configuration (no BFET)
- PROG Pin Setting (SW1)
- SW Pos: Cell Count
  1:            2 Cell (61.9k)
  2:            3 Cell (93.1k)
  3:            4 Cell (133k)
  4:            5 Cell (178k) <= default
  5:            6 Cell (237k)
  6:            7 Cell (316k)
- 2S-7S Board
  Configuration
- DISCLAIMER
- The entire information in this sheet is subject to change without notice.
  No part of the sheet may be copied or reproduced in any form or
  by any means without the prior written consent of Renesas Electronics Corporation.
  Renesas Electronics Corporation assumes no responsibility for any errors
  which may appear in this sheet. Renesas Electronics Corporation does not assume
  any liability for infringement of patents, copyrights or other intellectual property
  rights
  of third parties by arising from use of a device described herein
  or any other liability arising from use of such device.
  No license, either express, implied or otherwise, is granted under any patents,
  copyrights or other intellectual property rights of Renesas Electronics Corporation
  or others.
- ACLIM = 0.48A
- Rectifier Diode Ir should be less than 6 uA.
  (VBUS DC impedance condition is 115k ohm)
- Renesas Electronics Confidential
